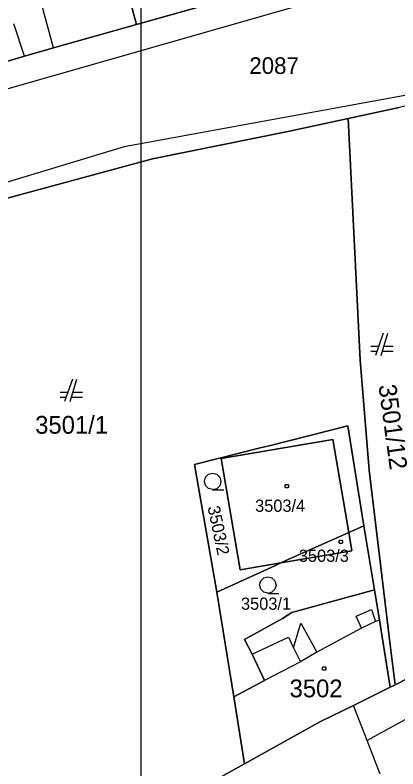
# Model space of a CAD drawing. Extents: x -263587 to -261993, y -1238795 to -1236748.
# Drawn here: x -263003.3 to -262968.9, y -1238314.4 to -1238246.6 of the extents above; entities that cross this region are included whole.
import ezdxf

# ---------------------------------------------------------------- set-up
doc = ezdxf.new("R2010")
doc.units = 0
for name, color, linetype in [('Vrstva 1', 7, 'Continuous'), ('Vrstva 3', 7, 'Continuous'), ('Vrstva 51', 7, 'Continuous')]:
    doc.layers.add(name, color=color, linetype=linetype)

msp = doc.modelspace()

# ---------------------------------------------------------------- linework, layer by layer
at = {"layer": 'Vrstva 1'}
for p, q in [((-262995.85, -1238234.66), (-262992.45, -1238247.47)), ((-262992.45, -1238247.47), (-262995.85, -1238234.66)), ((-262999.91, -1238249.59), (-263002.31, -1238240.58)), ((-262969.04, -1238240.88), (-262992.45, -1238247.47)), ((-262992.45, -1238247.47), (-262969.04, -1238240.88)), ((-262968.74, -1238243.17), (-263014.92, -1238256.39)), ((-263002.51, -1238250.33), (-263003.46, -1238247.42)), ((-262992.45, -1238247.47), (-262999.91, -1238249.59)), ((-262999.91, -1238249.59), (-262992.45, -1238247.47)), ((-262999.91, -1238249.59), (-263002.51, -1238250.33)), ((-263002.51, -1238250.33), (-262999.91, -1238249.59)), ((-262944.43, -1238249.47), (-262993.54, -1238258.48)), ((-263002.51, -1238250.33), (-263015.99, -1238254.37)), ((-263015.99, -1238254.37), (-263002.51, -1238250.33)), ((-262973.41, -1238255.92), (-262968.84, -1238254.94)), ((-262968.84, -1238254.94), (-262973.41, -1238255.92)), ((-262978.69, -1238257.06), (-262973.41, -1238255.92)), ((-262973.41, -1238255.92), (-262978.69, -1238257.06)), ((-262972.34, -1238277.67), (-262973.41, -1238255.92)), ((-262973.41, -1238255.92), (-262972.34, -1238277.67)), ((-262991, -1238259.57), (-262978.69, -1238257.06)), ((-262978.69, -1238257.06), (-262991, -1238259.57)), ((-262993.54, -1238258.48), (-263018.2, -1238265.93)), ((-263005.63, -1238263.53), (-262991, -1238259.57)), ((-262991, -1238259.57), (-263005.63, -1238263.53)), ((-262970.26, -1238275.25), (-262970.96, -1238277.25)), ((-262970.46, -1238277.25), (-262969.86, -1238275.25)), ((-262970.68, -1238276.45), (-262971.36, -1238276.45)), ((-262969.36, -1238276.45), (-262970.22, -1238276.45)), ((-262971.36, -1238276.85), (-262970.82, -1238276.85)), ((-262970.34, -1238276.85), (-262969.36, -1238276.85)), ((-262971.53, -1238287.56), (-262972.34, -1238277.67)), ((-262972.34, -1238277.67), (-262971.53, -1238287.56)), ((-262998.2, -1238279.38), (-262998.9, -1238281.38)), ((-262998.4, -1238281.38), (-262997.8, -1238279.38)), ((-262998.62, -1238280.58), (-262999.3, -1238280.58)), ((-262997.3, -1238280.58), (-262998.16, -1238280.58)), ((-262999.3, -1238280.98), (-262998.76, -1238280.98)), ((-262998.28, -1238280.98), (-262997.3, -1238280.98)), ((-262973.44, -1238283.58), (-262980.51, -1238285.37)), ((-262980.51, -1238285.37), (-262973.44, -1238283.58)), ((-262971.99, -1238292.55), (-262973.44, -1238283.58)), ((-262973.44, -1238283.58), (-262971.99, -1238292.55)), ((-262984.82, -1238286.52), (-262974.8, -1238284.81)), ((-262974.8, -1238284.81), (-262984.82, -1238286.52)), ((-262974.8, -1238284.81), (-262973.36, -1238293.16)), ((-262973.36, -1238293.16), (-262974.8, -1238284.81)), ((-262980.51, -1238285.37), (-262981.32, -1238285.56)), ((-262981.32, -1238285.56), (-262980.51, -1238285.37)), ((-262981.32, -1238285.56), (-262987.23, -1238287.06)), ((-262987.23, -1238287.06), (-262981.32, -1238285.56)), ((-262983.12, -1238296.53), (-262984.82, -1238286.52)), ((-262984.82, -1238286.52), (-262983.12, -1238296.53)), ((-262987.23, -1238287.06), (-262985.23, -1238298.52)), ((-262985.23, -1238298.52), (-262987.23, -1238287.06)), ((-262969.63, -1238303.27), (-262971.53, -1238287.56)), ((-262971.53, -1238287.56), (-262969.63, -1238303.27)), ((-262973.36, -1238293.16), (-262971.99, -1238292.55)), ((-262971.99, -1238292.55), (-262973.36, -1238293.16)), ((-262971.05, -1238298.31), (-262971.99, -1238292.55)), ((-262971.99, -1238292.55), (-262971.05, -1238298.31)), ((-262979.06, -1238295.71), (-262973.36, -1238293.16)), ((-262973.36, -1238293.16), (-262979.06, -1238295.71)), ((-262973.36, -1238293.16), (-262973.07, -1238294.82)), ((-262973.07, -1238294.82), (-262973.36, -1238293.16)), ((-262973.07, -1238294.82), (-262979.45, -1238295.9)), ((-262979.45, -1238295.9), (-262973.07, -1238294.82)), ((-262985.23, -1238298.52), (-262979.93, -1238296.14)), ((-262979.93, -1238296.14), (-262985.23, -1238298.52)), ((-262979.45, -1238295.9), (-262983.12, -1238296.53)), ((-262983.12, -1238296.53), (-262979.45, -1238295.9)), ((-262979.93, -1238296.14), (-262979.45, -1238295.9)), ((-262979.45, -1238295.9), (-262979.93, -1238296.14)), ((-262979.45, -1238295.9), (-262979.06, -1238295.71)), ((-262979.06, -1238295.71), (-262979.45, -1238295.9)), ((-262978.46, -1238300.36), (-262971.05, -1238298.31)), ((-262971.05, -1238298.31), (-262978.46, -1238300.36)), ((-262971.05, -1238298.31), (-262970.59, -1238301.03)), ((-262970.59, -1238301.03), (-262971.05, -1238298.31)), ((-262985.23, -1238298.52), (-262983.7, -1238307.95)), ((-262983.7, -1238307.95), (-262985.23, -1238298.52)), ((-262979.32, -1238300.88), (-262978.46, -1238300.36)), ((-262978.46, -1238300.36), (-262979.32, -1238300.88)), ((-262972.68, -1238300.67), (-262971.31, -1238300.09)), ((-262971.31, -1238300.09), (-262970.94, -1238301.16)), ((-262982.73, -1238302.78), (-262979.32, -1238300.88)), ((-262979.32, -1238300.88), (-262982.73, -1238302.78)), ((-262972.21, -1238301.77), (-262972.68, -1238300.67)), ((-262970.59, -1238301.03), (-262970.94, -1238301.16)), ((-262970.59, -1238301.03), (-262969.65, -1238307.07)), ((-262969.65, -1238307.07), (-262970.59, -1238301.03)), ((-262978.33, -1238303.54), (-262977.67, -1238301.3)), ((-262977.67, -1238301.3), (-262976.23, -1238303.93)), ((-262972.21, -1238301.77), (-262976.23, -1238303.93)), ((-262970.94, -1238301.16), (-262972.21, -1238301.77)), ((-262982.04, -1238304.1), (-262982.73, -1238302.78)), ((-262982.73, -1238302.78), (-262982.04, -1238304.1)), ((-262982.04, -1238304.1), (-262978.77, -1238302.56)), ((-262978.77, -1238302.56), (-262978.33, -1238303.54)), ((-262978.33, -1238303.54), (-262977.69, -1238304.8)), ((-262969.2, -1238306.85), (-262969.63, -1238303.27)), ((-262969.63, -1238303.27), (-262969.2, -1238306.85)), ((-262980.93, -1238306.47), (-262982.04, -1238304.1)), ((-262982.04, -1238304.1), (-262980.93, -1238306.47)), ((-262976.23, -1238303.93), (-262977.69, -1238304.8)), ((-262977.69, -1238304.8), (-262980.93, -1238306.47)), ((-262983.7, -1238307.95), (-262980.93, -1238306.47)), ((-262980.93, -1238306.47), (-262983.7, -1238307.95)), ((-262969.2, -1238306.85), (-262968.09, -1238306.3)), ((-262968.09, -1238306.3), (-262969.2, -1238306.85)), ((-262969.65, -1238307.07), (-262972.92, -1238308.72)), ((-262972.92, -1238308.72), (-262969.65, -1238307.07)), ((-262969.65, -1238307.07), (-262969.2, -1238306.85)), ((-262969.2, -1238306.85), (-262969.65, -1238307.07)), ((-262982.74, -1238313.95), (-262983.7, -1238307.95)), ((-262983.7, -1238307.95), (-262982.74, -1238313.95)), ((-262972.92, -1238308.72), (-262975.9, -1238310.15)), ((-262975.9, -1238310.15), (-262972.92, -1238308.72)), ((-262971.7, -1238311.86), (-262972.92, -1238308.72)), ((-262966.88, -1238309.21), (-262971.7, -1238311.86)), ((-262975.9, -1238310.15), (-262982.74, -1238313.95)), ((-262982.74, -1238313.95), (-262975.9, -1238310.15)), ((-262970.55, -1238314.89), (-262971.7, -1238311.86)), ((-262992.12, -1238319.17), (-262982.74, -1238313.95)), ((-262982.74, -1238313.95), (-262992.12, -1238319.17))]:
    msp.add_line(p, q, dxfattribs=at)
for points in [[(-262985.58, -1238289.3), (-262985.96, -1238289.2), (-262986.23, -1238288.93), (-262986.33, -1238288.56), (-262986.23, -1238288.19), (-262985.96, -1238287.92), (-262985.59, -1238287.82), (-262985.22, -1238287.92), (-262984.95, -1238288.19), (-262984.85, -1238288.57), (-262984.95, -1238288.95), (-262985.22, -1238289.22), (-262985.6, -1238289.32), (-262984.6, -1238289.32)], [(-262980.62, -1238298.62), (-262981, -1238298.52), (-262981.27, -1238298.25), (-262981.37, -1238297.88), (-262981.27, -1238297.51), (-262981, -1238297.24), (-262980.63, -1238297.14), (-262980.26, -1238297.24), (-262979.99, -1238297.51), (-262979.89, -1238297.89), (-262979.99, -1238298.27), (-262980.26, -1238298.54), (-262980.64, -1238298.64), (-262979.64, -1238298.64)]]:
    msp.add_lwpolyline(points, dxfattribs=at)
for points in [[(-262978.84, -1238288.85), (-262978.75, -1238289), (-262978.84, -1238289.15), (-262979.02, -1238289.15), (-262979.11, -1238289), (-262979.02, -1238288.85)], [(-262973.98, -1238293.86), (-262973.89, -1238294.01), (-262973.98, -1238294.16), (-262974.16, -1238294.16), (-262974.25, -1238294.01), (-262974.16, -1238293.86)], [(-262975.48, -1238305.25), (-262975.39, -1238305.4), (-262975.48, -1238305.55), (-262975.66, -1238305.55), (-262975.75, -1238305.4), (-262975.66, -1238305.25)]]:
    msp.add_lwpolyline(points, close=True, dxfattribs=at)
at = {"layer": 'Vrstva 3'}
msp.add_lwpolyline([(-262912.88, -1238240.83), (-262914.78, -1238249.25), (-262914.91, -1238250.99), (-262915.44, -1238253.09), (-262944.92, -1238251.91), (-262949.15, -1238253.18), (-262968.33, -1238254.83), (-262968.84, -1238254.94), (-262973.41, -1238255.92), (-262978.69, -1238257.06), (-262991, -1238259.57), (-263005.63, -1238263.53), (-263021.23, -1238269.49), (-263036.8, -1238276.02), (-263038.91, -1238277.059), (-263040.01, -1238274.19), (-263041.7, -1238270.52), (-263045.31, -1238265.66), (-263015.99, -1238254.37), (-263002.51, -1238250.33), (-262999.91, -1238249.59), (-262992.45, -1238247.47), (-262969.04, -1238240.88)], dxfattribs=at)
at = {"layer": 'Vrstva 51'}
msp.add_lwpolyline([(-262992.03, -1237088.09), (-262695.03, -1237088.09), (-262695.03, -1238768.09), (-262992.03, -1238768.09)], close=True, dxfattribs=at)

# ---------------------------------------------------------------- texts
at = {"layer": 'Vrstva 1'}
for s, height, rotation, p in [('3501/12', 1.6, 277.71264, (-262970.691, -1238279.937)), ('3503/2', 1.1, 281.83794, (-262986.056, -1238290.881))]:
    msp.add_text(s, height=height, rotation=rotation, dxfattribs=at).set_placement(p)
for s, height, p in [('3501/1', 1.6, (-263001.54, -1238284.28)), ('3503/4', 1.1, (-262981.775, -1238291.3)), ('3503/3', 1.1, (-262977.845, -1238295.8)), ('3503/1', 1.1, (-262983.045, -1238300.11)), ('3502', 1.6, (-262978.677, -1238307.98))]:
    msp.add_text(s, height=height, dxfattribs=at).set_placement(p)
at = {"layer": 'Vrstva 3'}
msp.add_text('2087', height=1.5, dxfattribs=at).set_placement((-262982.301, -1238251.93))

doc.saveas('drawing.dxf')
